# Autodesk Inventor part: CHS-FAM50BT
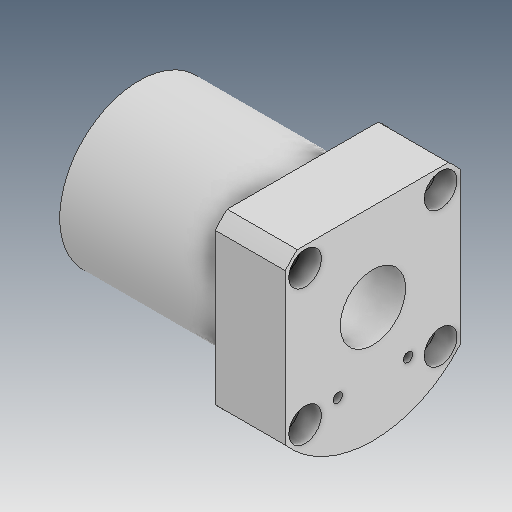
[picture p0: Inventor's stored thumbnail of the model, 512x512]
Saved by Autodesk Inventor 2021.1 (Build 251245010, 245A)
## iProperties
Created: 2019-04
Part Number: CHS-FAM50BT
Material: Ogólny
Document SubType Name: Modeling
Designer: user
Density: 1 g/cm^3
Appearance: Domyślna
Author: user
Revision Number: ÈÎºÎ
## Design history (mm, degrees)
feature "ÊäÈë1"
node "Bryła1"
